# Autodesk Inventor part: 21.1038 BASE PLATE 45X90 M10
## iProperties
Created: 2007-03
Part Number: 21.1038 BASE PLATE 45X90 M10
Document SubType Name: Modeling
Designer: Andy Moles
Material: Aluminum-6061
Mass: 151.725 g
Surface Area: 129.023 cm^2
Volume: 55.9872 cm^3
Density: 2.71 g/cm^3
Author: Andy Moles
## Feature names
1. Extrusion1
2. Hole1
3. Hole2
4. Fillet1
